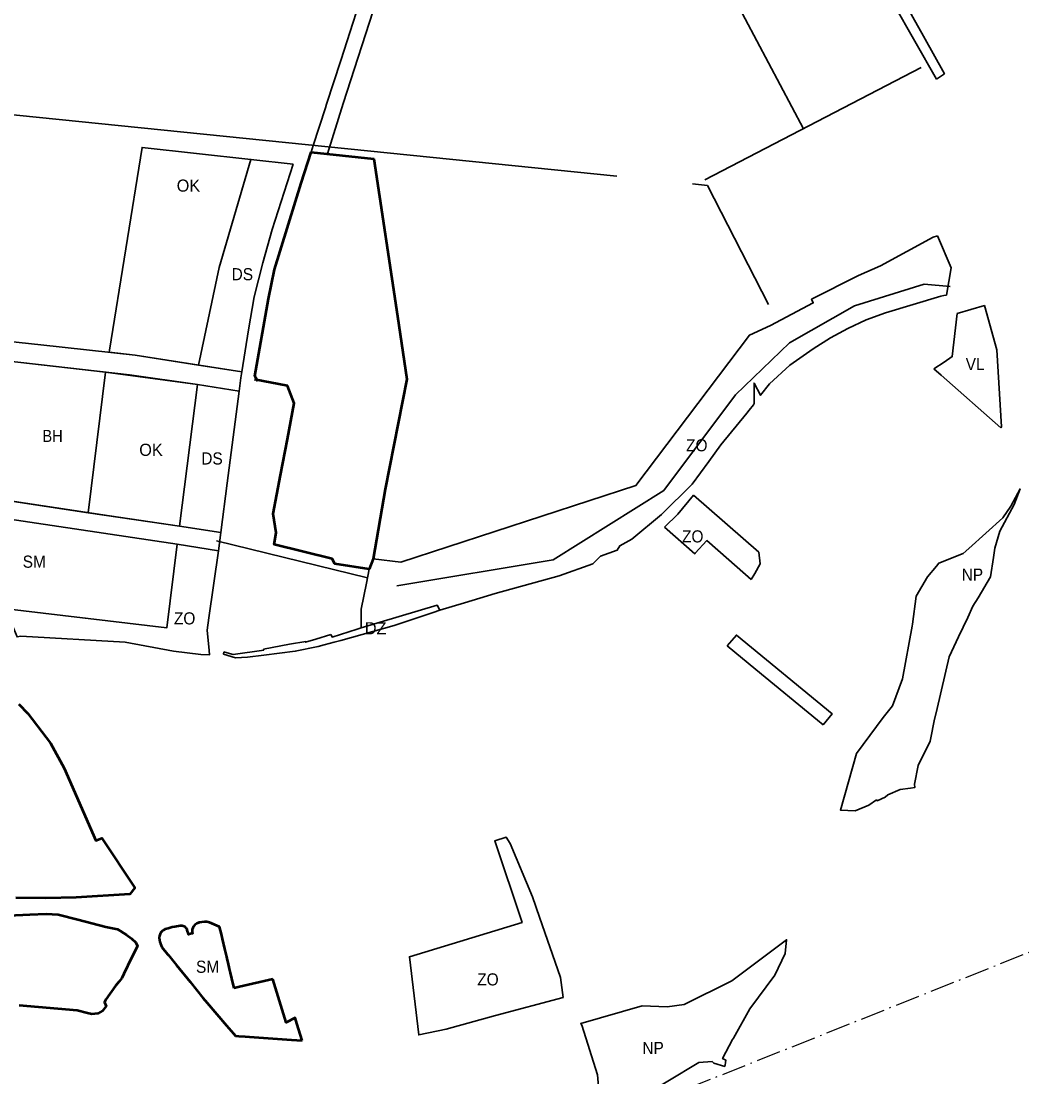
# Model space of a CAD drawing. Extents: x -650276 to -642489, y -1074311 to -1066658.
# Drawn here: x -646929 to -645941, y -1070271 to -1069228 of the extents above; entities that cross this region are included whole.
import ezdxf

# ---------------------------------------------------------------- set-up
doc = ezdxf.new("R2010")
doc.units = 0
doc.header["$LTSCALE"] = 4.8
doc.linetypes.add('DOT_DASHED', pattern=[7.7, 5, -1.2, 0.3, -1.2])
for name, color, linetype, lineweight in [('1', 7, 'Continuous', 35), ('13', 7, 'Continuous', 35), ('15', 7, 'Continuous', 35), ('18', 7, 'Continuous', 35), ('24', 7, 'Continuous', 35), ('25', 7, 'Continuous', 35), ('34', 7, 'Continuous', 35), ('42', 7, 'Continuous', 35), ('48', 7, 'Continuous', 35), ('54', 7, 'Continuous', 35), ('55', 7, 'Continuous', 53), ('60', 7, 'Continuous', 53)]:
    doc.layers.add(name, color=color, linetype=linetype, lineweight=lineweight)
doc.layers.add('62', color=7, linetype='Continuous')
doc.layers.add('63', color=7, linetype='Continuous')

msp = doc.modelspace()

# ---------------------------------------------------------------- linework, layer by layer
at = {"layer": '1'}
msp.add_lwpolyline([(-646944.168, -1069563.743), (-647047.648, -1069552.245), (-647061.304, -1069551.773), (-647060.7, -1069683.894), (-646863, -1069714), (-646846, -1069575)], close=True, dxfattribs=at)
at = {"layer": '13'}
for points in [[(-646816.615, -1069558.064), (-646754.066, -1069567.993), (-646733.74, -1069471.688), (-646733.74, -1069471.688), (-646702.425, -1069364.771), (-646702.425, -1069364.771), (-646702.425, -1069364.771), (-646702.425, -1069364.771), (-646702.425, -1069364.771), (-646809.879, -1069353.002), (-646842.103, -1069553.182), (-646842.441, -1069555.283), (-646816.615, -1069558.064)], [(-646772.906, -1069727.176), (-646755.269, -1069587.04), (-646846, -1069575), (-646863, -1069714)]]:
    msp.add_lwpolyline(points, close=True, dxfattribs=at)
at = {"layer": '15'}
msp.add_line((-646142.68, -1069918.62), (-646136.88, -1069923.39), dxfattribs=at)
for points in [[(-646037.99, -1069242.88), (-646107, -1069119.41), (-646150.87, -1069037.64), (-646152.26, -1069038.76), (-646161.484, -1069046.228), (-646153.307, -1069059.947), (-646025.14, -1069285.394)], [(-646025.14, -1069285.394), (-646017.15, -1069280.19), (-646037.99, -1069242.88)], [(-646944.167, -1069563.743), (-646822.169, -1069577.72), (-646755.269, -1069587.04), (-646714.037, -1069593.585), (-646712.34, -1069580.49), (-646711.444, -1069574.771), (-646711.442, -1069574.759), (-646816.615, -1069558.064), (-646910.029, -1069548.006), (-646986.633, -1069539.757)], [(-647060.617, -1069702.116), (-646998.56, -1069711.443), (-646993.771, -1069712.163), (-646775.286, -1069745.022), (-646734.48, -1069751.35), (-646732.143, -1069733.308), (-646772.906, -1069727.176), (-646842.148, -1069716.763), (-647060.7, -1069683.894), (-647061.304, -1069551.773), (-647083.356, -1069551.018)], [(-646136.88, -1069923.39), (-646127.987, -1069912.574), (-646222.694, -1069834.722), (-646231.73, -1069845.42)], [(-646231.73, -1069845.42), (-646203.48, -1069868.65), (-646142.68, -1069918.62)]]:
    msp.add_lwpolyline(points, dxfattribs=at)
at = {"layer": '18'}
msp.add_lwpolyline([(-646785.437, -1069827.534), (-646775.286, -1069745.022), (-646993.771, -1069712.163), (-646981.92, -1069734.86), (-646946.369, -1069808.291)], close=True, dxfattribs=at)
for points in [[(-646934.63, -1070094.24), (-646904.97, -1070094.52), (-646874.9, -1070094.1), (-646859.29, -1070093.1), (-646821.89, -1070090.7), (-646817.15, -1070084.76), (-646816.9, -1070084.45), (-646837.65, -1070053.22), (-646849.79, -1070035.17), (-646855.62, -1070037.66), (-646886.85, -1069966.26), (-646900.26, -1069941.64), (-646904.72, -1069935.84), (-646922.79, -1069912.31), (-646931.67, -1069902.89)], [(-646748.31, -1070117.83), (-646753.45, -1070118.63), (-646755.74, -1070119.56), (-646757.76, -1070121.07), (-646759.06, -1070122.6), (-646759.78, -1070124), (-646760.32, -1070125.55), (-646760.5, -1070127.58), (-646760.22, -1070129.42), (-646762.07, -1070129.91), (-646763.9, -1070130.41), (-646763.98, -1070130.1), (-646764, -1070129.86), (-646764.94, -1070127.21), (-646765.19, -1070126.23), (-646765.51, -1070125.28), (-646765.97, -1070124.42), (-646767.38, -1070123), (-646768.25, -1070122.53), (-646769.17, -1070122.15), (-646770.43, -1070121.92), (-646772.19, -1070121.98), (-646777.37, -1070122.79), (-646780.28, -1070123.41), (-646784.13, -1070124.41), (-646787, -1070125.38), (-646788.77, -1070126.26), (-646789.61, -1070126.79), (-646791.03, -1070128.23)], [(-646718.8, -1070183.56), (-646721.09, -1070173.94), (-646722.4, -1070168.45), (-646723.4, -1070164.29), (-646724.86, -1070158.17), (-646725.39, -1070155.78), (-646726.17, -1070152.7), (-646728.14, -1070144.51), (-646730.45, -1070134.85), (-646731.54, -1070130.28), (-646733.35, -1070122.79), (-646740.92, -1070119.57), (-646743.33, -1070118.51), (-646745.78, -1070117.96), (-646748.31, -1070117.83)], [(-646791.03, -1070128.23), (-646791.64, -1070129), (-646792.11, -1070129.89), (-646792.76, -1070131.79), (-646792.97, -1070133.76), (-646792.84, -1070135.73), (-646792.42, -1070137.71), (-646792.18, -1070138.48), (-646791.84, -1070139.56), (-646791.13, -1070141.44), (-646790.86, -1070142.02), (-646790.29, -1070142.85), (-646784.8, -1070149.86), (-646784.45, -1070150.291)], [(-646784.45, -1070150.291), (-646784.18, -1070150.61), (-646783.937, -1070150.923), (-646775.93, -1070160.78), (-646762.52, -1070177.24)], [(-646680.68, -1070174.5), (-646713.74, -1070182.36), (-646718.8, -1070183.56)], [(-646651.86, -1070235.22), (-646656.96, -1070218.43), (-646658.64, -1070212.77), (-646667.64, -1070217.36), (-646680.61, -1070174.79), (-646680.68, -1070174.5)], [(-646762.52, -1070177.24), (-646749.79, -1070193.02), (-646745.61, -1070198.15), (-646726.48, -1070220.46), (-646726.36, -1070220.34), (-646719.7, -1070228.25), (-646717.71, -1070230.56)], [(-646717.71, -1070230.56), (-646714.42, -1070230.81), (-646708.2, -1070231.25), (-646703.67, -1070231.58), (-646662.41, -1070234.57), (-646651.86, -1070235.22)]]:
    msp.add_lwpolyline(points, dxfattribs=at)
at = {"layer": '24'}
msp.add_line((-646772.907, -1069727.177), (-646732.143, -1069733.308), dxfattribs=at)
msp.add_lwpolyline([(-646660.526, -1069369.36), (-646702.425, -1069364.771), (-646733.74, -1069471.688), (-646754.066, -1069567.993), (-646711.442, -1069574.759), (-646704.68, -1069533.06), (-646699.07, -1069500.57), (-646690.51, -1069466.97), (-646681.5, -1069434.17)], close=True, dxfattribs=at)
for points in [[(-646725.82, -1069684.5), (-646714.037, -1069593.585), (-646755.269, -1069587.04), (-646772.907, -1069727.177)], [(-646732.143, -1069733.308), (-646725.82, -1069684.5), (-646725.82, -1069684.5)]]:
    msp.add_lwpolyline(points, dxfattribs=at)
at = {"layer": '25'}
msp.add_line((-646729.54, -1069853.69), (-646729.24, -1069851.41), dxfattribs=at)
for points in [[(-646515.63, -1069810.24), (-646522.32, -1069812.28), (-646560.92, -1069825.33), (-646613.65, -1069840.02), (-646620.06, -1069841.69), (-646629.83, -1069844.23), (-646635.93, -1069845.82), (-646658.5, -1069850.59), (-646689.73, -1069854.58), (-646705.87, -1069856.62), (-646717.66, -1069857.11), (-646729.54, -1069853.69)], [(-646593.34, -1069827.68), (-646518.19, -1069805.27), (-646515.63, -1069810.24)], [(-646623.31, -1069834.1), (-646622.54, -1069835.88), (-646622.19, -1069836.71), (-646597.29, -1069828.86), (-646593.34, -1069827.68)], [(-646729.24, -1069851.41), (-646723.5, -1069852.83), (-646719.82, -1069853.78), (-646689.63, -1069849.7), (-646689.8, -1069848.71), (-646664.22, -1069843.72), (-646648.18, -1069841.04), (-646648.28, -1069841.78), (-646638.34, -1069838.73), (-646623.31, -1069834.1)]]:
    msp.add_lwpolyline(points, dxfattribs=at)
at = {"layer": '34'}
for points in [[(-646027.49, -1069571.79), (-646017.39, -1069564.94), (-646009.52, -1069559.6), (-646004.7, -1069517.16)], [(-646004.7, -1069517.16), (-645977.73, -1069509.11), (-645965.36, -1069552.99), (-645960.78, -1069628.91), (-645961.36, -1069630.05)], [(-645961.36, -1069630.05), (-646020.4, -1069578.04), (-646027.49, -1069571.79)]]:
    msp.add_lwpolyline(points, dxfattribs=at)
at = {"layer": '42'}
msp.add_line((-646230.3, -1069760.5), (-646208.135, -1069779.937), dxfattribs=at)
for points in [[(-646589.56, -1069192.07), (-646601.41, -1069229.34), (-646613.6, -1069267.04), (-646627.59, -1069310.34), (-646628.66, -1069313.66), (-646640.715, -1069350.951), (-646642.89, -1069357.68), (-646626.774, -1069359.349), (-646611.107, -1069309.68), (-646577.878, -1069206.485)], [(-646023.96, -1069440.34), (-646028.16, -1069441.58), (-646080.35, -1069469.89), (-646102.15, -1069479.49), (-646148.5, -1069503), (-646146.8, -1069506.6), (-646189.17, -1069528.74), (-646209.9, -1069538.5), (-646321.973, -1069686.855), (-646554.262, -1069762.602), (-646581.489, -1069759.421), (-646585.51, -1069769.57)], [(-646017.63, -1069499.08), (-646017.63, -1069499.08), (-646015.16, -1069498.74), (-646010.65, -1069471.91), (-646023.96, -1069440.34)], [(-646491.18, -1069802.78), (-646491.18, -1069802.78), (-646460.97, -1069793.56), (-646397.74, -1069776.29), (-646364.67, -1069764.23), (-646357, -1069756.7), (-646340.48, -1069750.92), (-646337.97, -1069746.4), (-646325.92, -1069740.05), (-646296.64, -1069715.72), (-646266.27, -1069685.75), (-646250, -1069663.09), (-646238.19, -1069646.63), (-646212.43, -1069615.33), (-646210.03, -1069612.42), (-646205.9, -1069607.17), (-646205, -1069606.03), (-646205.25, -1069585.67), (-646198.82, -1069597.83), (-646190.07, -1069586.48), (-646169.9, -1069568.04), (-646146.81, -1069551.97), (-646129.87, -1069541.19), (-646112.56, -1069531.78), (-646094.39, -1069523.34), (-646075.48, -1069516.38), (-646020.75, -1069500), (-646017.63, -1069499.08)], [(-646265.02, -1069696.43), (-646280.5, -1069715.27), (-646293.76, -1069728)], [(-646208.135, -1069779.937), (-646204.6, -1069773.78), (-646199.17, -1069764.33), (-646200.67, -1069752.88), (-646265.02, -1069696.43)], [(-646293.76, -1069728), (-646263.929, -1069754.309), (-646263.36, -1069753.69), (-646252.07, -1069741.41), (-646230.3, -1069760.5)], [(-646585.51, -1069769.57), (-646588.25, -1069783.37), (-646593.34, -1069808.99), (-646593.34, -1069827.68)], [(-646593.34, -1069827.68), (-646518.19, -1069805.27), (-646515.63, -1069810.24), (-646491.18, -1069802.78)], [(-646417.23, -1070113.25), (-646424.17, -1070093.21), (-646446.21, -1070040.55), (-646450.22, -1070034.31), (-646461.415, -1070037.991), (-646434.503, -1070118.512), (-646545.78, -1070152.41), (-646536.47, -1070229.65), (-646509.31, -1070224.11), (-646460.8, -1070210.57)], [(-646460.8, -1070210.57), (-646393.97, -1070192.69), (-646396.51, -1070173.06), (-646417.23, -1070113.25)]]:
    msp.add_lwpolyline(points, dxfattribs=at)
msp.add_lwpolyline([(-646775.286, -1069745.022), (-646785.437, -1069827.534), (-646946.369, -1069808.291), (-646936.6, -1069828.47), (-646933.39, -1069836.51), (-646929.67, -1069835.68), (-646826.63, -1069841.84), (-646778.74, -1069850.44), (-646751.8, -1069853.72), (-646743.31, -1069854.26), (-646743.7, -1069850.07), (-646745.56, -1069829.84), (-646743.85, -1069817.72), (-646734.48, -1069751.35)], close=True, dxfattribs=at)
at = {"layer": '48'}
msp.add_lwpolyline([(-646050.68, -1069985.78), (-646046.28, -1069985.18), (-646046.63, -1069982.04), (-646043.2, -1069963.46), (-646031.24, -1069939.45), (-646030.62, -1069936.3), (-646027.3, -1069919.47), (-646024.41, -1069907.23), (-646012.37, -1069856.22), (-646003.18, -1069836.56), (-645993.96, -1069817.23), (-645989.01, -1069806.25), (-645983.89, -1069797.86), (-645971.7, -1069777.05), (-645968.78, -1069758.13), (-645967.35, -1069748.81), (-645962.48, -1069732.04), (-645948.22, -1069705.79), (-645942.41, -1069690.26), (-645951.52, -1069707.28), (-645959.63, -1069718.95), (-645993.22, -1069749.24), (-645998.57, -1069754.06), (-646022.72, -1069763.59), (-646025.11, -1069766.63), (-646034.02, -1069777.19), (-646044.94, -1069796.35), (-646048.71, -1069823.79), (-646049, -1069825.93), (-646058.71, -1069877.82), (-646068.5, -1069904.5), (-646077.78, -1069916.11), (-646104.04, -1069951.75), (-646119.95, -1070007.73), (-646105.35, -1070008.18), (-646091.87, -1070002.66), (-646084.39, -1069997.53), (-646083.67, -1069998.4), (-646075.69, -1069994.68), (-646073.1, -1069992.61), (-646060.94, -1069987.19)], close=True, dxfattribs=at)
msp.add_lwpolyline([(-646321.24, -1070293.85), (-646259.91, -1070256.89), (-646246.71, -1070255.96), (-646245.02, -1070257.65), (-646234.17, -1070260.88), (-646233.69, -1070259.57), (-646233.36, -1070257.04), (-646233.06, -1070254.74), (-646236.44, -1070253.13), (-646226.42, -1070234.23), (-646225.7, -1070232.93), (-646209.55, -1070203.85), (-646184.67, -1070170.61), (-646174.62, -1070149.28), (-646173.2, -1070135.64), (-646227.29, -1070176.24), (-646274.26, -1070199.6), (-646291.14, -1070202.1), (-646315.95, -1070201.09), (-646376.5, -1070218.32), (-646375.52, -1070220.21), (-646359.89, -1070269.01), (-646357.73, -1070296.13)], dxfattribs=at)
at = {"layer": '54'}
for p, q in [((-646261, -1069137), (-646156.539, -1069334.511)), ((-646253.953, -1069385.091), (-646040, -1069274)), ((-646340.757, -1069381.428), (-647038.68, -1069310.312)), ((-646251.153, -1069390.558), (-646266.005, -1069389.045)), ((-646251.153, -1069390.558), (-646191, -1069508)), ((-646736.301, -1069741.493), (-646587.205, -1069778.112))]:
    msp.add_line(p, q, dxfattribs=at)
msp.add_lwpolyline([(-646558.043, -1069786.029), (-646403.749, -1069760.313), (-646294.458, -1069691.739), (-646223.741, -1069597.448), (-646170.167, -1069546.017), (-646105.878, -1069509.587), (-646037.303, -1069488.157), (-646011.588, -1069490.3)], dxfattribs=at)
at = {"layer": '55', "linetype": 'DOT_DASHED', "lineweight": 25}
msp.add_line((-647060.176, -1070597.455), (-645765.418, -1070080.935), dxfattribs=at)
at = {"layer": '60'}
for points in [[(-646695.61, -1069583.8), (-646698.4, -1069578.93), (-646684.95, -1069502.53), (-646679.13, -1069473.51), (-646652.72, -1069388.08), (-646642.89, -1069357.68), (-646580.797, -1069364.111), (-646557.39, -1069519.61), (-646548.41, -1069582.03), (-646569.86, -1069690.67), (-646581.489, -1069759.421), (-646585.51, -1069769.57), (-646619.49, -1069764.46), (-646622, -1069759.34), (-646679.46, -1069745.37), (-646677.36, -1069733.65), (-646680.28, -1069714.83), (-646673, -1069676.8), (-646666.26, -1069641.2), (-646659.52, -1069605.53), (-646666.36, -1069588.57), (-646698.96, -1069582.26)], [(-646931.67, -1069902.89), (-646922.79, -1069912.31), (-646904.72, -1069935.84), (-646900.26, -1069941.64), (-646886.85, -1069966.26), (-646855.62, -1070037.66), (-646849.79, -1070035.17), (-646816.9, -1070084.45), (-646821.89, -1070090.7), (-646874.9, -1070094.1), (-646904.97, -1070094.52), (-646934.63, -1070094.24)], [(-646941.99, -1070111.74), (-646920.68, -1070110.58), (-646904.66, -1070110.24), (-646892.87, -1070110.82), (-646873.5, -1070115.8), (-646845.78, -1070122.84), (-646834.04, -1070125.34), (-646825.4, -1070130.78), (-646820.35, -1070134.43), (-646816.06, -1070138.5), (-646814.53, -1070141.96), (-646820.51, -1070153.68), (-646827.95, -1070169.52), (-646829.87, -1070173.61), (-646832.62, -1070177.08), (-646836.06, -1070181.31), (-646845.76, -1070194.67), (-646847.17, -1070197.38), (-646845.3, -1070201.3), (-646849.15, -1070205.9), (-646853.67, -1070208.44), (-646859.54, -1070209.09), (-646863.66, -1070208.37), (-646874.04, -1070205.5), (-646931.25, -1070200.56)], [(-646748.31, -1070117.83), (-646753.45, -1070118.63), (-646755.74, -1070119.56), (-646757.76, -1070121.07), (-646759.06, -1070122.6), (-646759.78, -1070124), (-646760.32, -1070125.55), (-646760.5, -1070127.58), (-646760.22, -1070129.42), (-646762.07, -1070129.91), (-646763.9, -1070130.41), (-646763.98, -1070130.1), (-646764, -1070129.86), (-646764.94, -1070127.21), (-646765.19, -1070126.23), (-646765.51, -1070125.28), (-646765.97, -1070124.42), (-646767.38, -1070123), (-646768.25, -1070122.53), (-646769.17, -1070122.15), (-646770.43, -1070121.92), (-646772.19, -1070121.98), (-646777.37, -1070122.79), (-646780.28, -1070123.41), (-646784.13, -1070124.41), (-646787, -1070125.38), (-646788.77, -1070126.26), (-646789.61, -1070126.79), (-646791.03, -1070128.23)], [(-646748.31, -1070117.83), (-646753.45, -1070118.63), (-646755.74, -1070119.56), (-646757.76, -1070121.07), (-646759.06, -1070122.6), (-646759.78, -1070124), (-646760.32, -1070125.55), (-646760.5, -1070127.58), (-646760.22, -1070129.42), (-646762.07, -1070129.91), (-646763.9, -1070130.41), (-646763.98, -1070130.1), (-646764, -1070129.86), (-646764.94, -1070127.21), (-646765.19, -1070126.23), (-646765.51, -1070125.28), (-646765.97, -1070124.42), (-646767.38, -1070123), (-646768.25, -1070122.53), (-646769.17, -1070122.15), (-646770.43, -1070121.92), (-646772.19, -1070121.98), (-646777.37, -1070122.79), (-646780.28, -1070123.41), (-646784.13, -1070124.41), (-646787, -1070125.38), (-646788.77, -1070126.26), (-646789.61, -1070126.79), (-646791.03, -1070128.23)], [(-646718.8, -1070183.56), (-646721.09, -1070173.94), (-646722.4, -1070168.45), (-646723.4, -1070164.29), (-646724.86, -1070158.17), (-646725.39, -1070155.78), (-646726.17, -1070152.7), (-646728.14, -1070144.51), (-646730.45, -1070134.85), (-646731.54, -1070130.28), (-646733.35, -1070122.79), (-646740.92, -1070119.57), (-646743.33, -1070118.51), (-646745.78, -1070117.96), (-646748.31, -1070117.83)], [(-646718.8, -1070183.56), (-646721.09, -1070173.94), (-646722.4, -1070168.45), (-646723.4, -1070164.29), (-646724.86, -1070158.17), (-646725.39, -1070155.78), (-646726.17, -1070152.7), (-646728.14, -1070144.51), (-646730.45, -1070134.85), (-646731.54, -1070130.28), (-646733.35, -1070122.79), (-646740.92, -1070119.57), (-646743.33, -1070118.51), (-646745.78, -1070117.96), (-646748.31, -1070117.83)], [(-646791.03, -1070128.23), (-646791.64, -1070129), (-646792.11, -1070129.89), (-646792.76, -1070131.79), (-646792.97, -1070133.76), (-646792.84, -1070135.73), (-646792.42, -1070137.71), (-646792.18, -1070138.48), (-646791.84, -1070139.56), (-646791.13, -1070141.44), (-646790.86, -1070142.02), (-646790.29, -1070142.85), (-646784.8, -1070149.86), (-646784.45, -1070150.291)], [(-646791.03, -1070128.23), (-646791.64, -1070129), (-646792.11, -1070129.89), (-646792.76, -1070131.79), (-646792.97, -1070133.76), (-646792.84, -1070135.73), (-646792.42, -1070137.71), (-646792.18, -1070138.48), (-646791.84, -1070139.56), (-646791.13, -1070141.44), (-646790.86, -1070142.02), (-646790.29, -1070142.85), (-646784.8, -1070149.86), (-646784.45, -1070150.291)], [(-646784.45, -1070150.291), (-646784.18, -1070150.61), (-646783.937, -1070150.923), (-646775.93, -1070160.78), (-646762.52, -1070177.24)], [(-646784.45, -1070150.291), (-646784.18, -1070150.61), (-646783.937, -1070150.923), (-646775.93, -1070160.78), (-646762.52, -1070177.24)], [(-646680.68, -1070174.5), (-646713.74, -1070182.36), (-646718.8, -1070183.56)], [(-646680.68, -1070174.5), (-646713.74, -1070182.36), (-646718.8, -1070183.56)], [(-646651.86, -1070235.22), (-646656.96, -1070218.43), (-646658.64, -1070212.77), (-646667.64, -1070217.36), (-646680.61, -1070174.79), (-646680.68, -1070174.5)], [(-646651.86, -1070235.22), (-646656.96, -1070218.43), (-646658.64, -1070212.77), (-646667.64, -1070217.36), (-646680.61, -1070174.79), (-646680.68, -1070174.5)], [(-646762.52, -1070177.24), (-646749.79, -1070193.02), (-646745.61, -1070198.15), (-646726.48, -1070220.46), (-646726.36, -1070220.34), (-646719.7, -1070228.25), (-646717.71, -1070230.56)], [(-646762.52, -1070177.24), (-646749.79, -1070193.02), (-646745.61, -1070198.15), (-646726.48, -1070220.46), (-646726.36, -1070220.34), (-646719.7, -1070228.25), (-646717.71, -1070230.56)], [(-646717.71, -1070230.56), (-646714.42, -1070230.81), (-646708.2, -1070231.25), (-646703.67, -1070231.58), (-646662.41, -1070234.57), (-646651.86, -1070235.22)], [(-646717.71, -1070230.56), (-646714.42, -1070230.81), (-646708.2, -1070231.25), (-646703.67, -1070231.58), (-646662.41, -1070234.57), (-646651.86, -1070235.22)]]:
    msp.add_lwpolyline(points, dxfattribs=at)

# ---------------------------------------------------------------- texts
at = {"layer": '62'}
for s, p in [('OK', (-646775.694, -1069396.644)), ('OK', (-646812.694, -1069657.644)), ('DZ', (-646589.843, -1069833.949))]:
    msp.add_text(s, height=12, dxfattribs=at).set_placement(p)
for s, width, p in [('DS', 0.95, (-646721.423, -1069484.188)), ('BH', 0.9, (-646908.386, -1069643.937)), ('ZO', 0.95, (-646272.423, -1069653.188)), ('DS', 0.95, (-646751.423, -1069666.188)), ('ZO', 0.95, (-646276.423, -1069743.188)), ('SM', 0.95, (-646927.837, -1069768.153)), ('NP', 0.95, (-646000.15, -1069780.972)), ('ZO', 0.95, (-646778.423, -1069824.188)), ('ZO', 0.95, (-646478.758, -1070180.853)), ('NP', 0.95, (-646315.631, -1070248.579))]:
    msp.add_text(s, height=12, dxfattribs=dict(at, width=width)).set_placement(p)
at = {"layer": '63', "width": 0.95}
for s, p in [('VL', (-645996.15, -1069572.972)), ('SM', (-646756.615, -1070168.352))]:
    msp.add_text(s, height=12, dxfattribs=at).set_placement(p)

doc.saveas('drawing.dxf')
